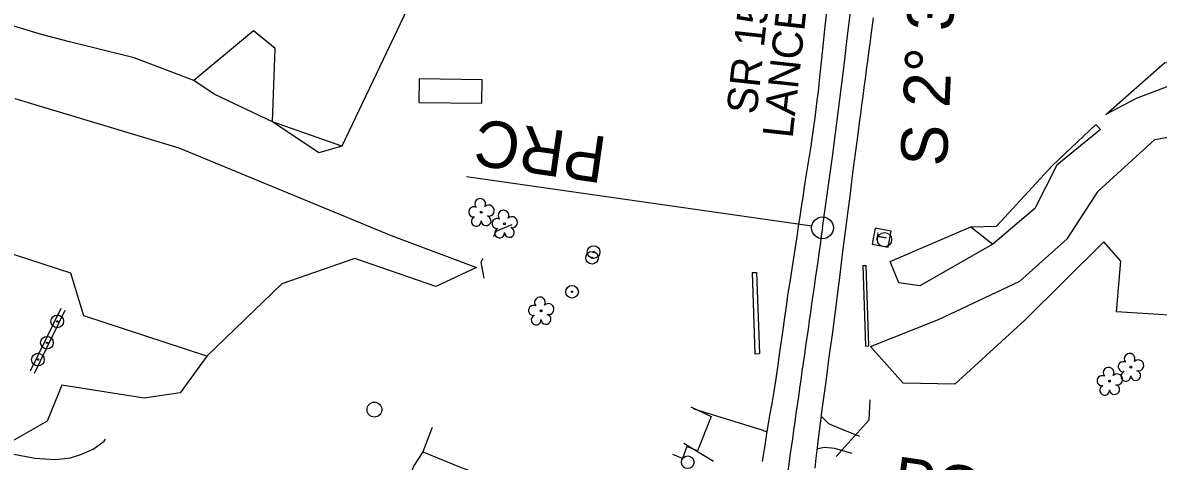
# Model space of a CAD drawing. Extents: x 478596 to 483012, y 490885 to 495165.
# Drawn here: x 480534.5 to 480925.2, y 493300.7 to 493451.6 of the extents above; entities that cross this region are included whole.
import ezdxf

# ---------------------------------------------------------------- set-up
doc = ezdxf.new("R2010")
doc.units = 0
for name, color, linetype in [('Exist Guardrail', 7, 'Continuous'), ('Exist Horizontal Alignment', 7, 'Continuous'), ('Exist Horizontal Alignment Direction Label', 7, 'Continuous'), ('Exist Other Culture AG Tank', 7, 'Continuous'), ('Exist Other Culture Area Outline', 7, 'Continuous'), ('Exist Other Culture Fence Line', 7, 'Continuous'), ('Exist Other Culture Gate', 7, 'Continuous'), ('Exist Other Culture Sign', 7, 'Continuous'), ('Exist Other Culture Sign Post CELL', 7, 'Continuous'), ('Exist Other Culture Well CELL', 7, 'Continuous'), ('Exist Roads Change in Surface', 7, 'Continuous'), ('Exist Roads EOP', 7, 'Continuous'), ('Exist Roads EOP Other', 7, 'Continuous'), ('Exist Roads EOP Text', 7, 'Continuous'), ('Exist Roads Soil', 7, 'Continuous'), ('Exist Structure Major Bridge WW', 7, 'Continuous'), ('Exist Structure Minor Head and End Wall', 7, 'Continuous'), ('Exist Utilities Other Located Object CELL', 7, 'Continuous'), ('Exist Utilities Other Pole CELL', 7, 'Continuous'), ('Exist Utilities Telephone Pedestal CELL', 7, 'Continuous'), ('Exist Vegetation Hedge Row', 7, 'Continuous'), ('Exist Vegetation Tree CELL', 7, 'Continuous'), ('Exist Vegetation Woods Line', 7, 'Continuous')]:
    doc.layers.add(name, color=color, linetype=linetype)

msp = doc.modelspace()

# ---------------------------------------------------------------- linework, layer by layer
at = {"layer": 'Exist Guardrail'}
msp.add_lwpolyline([(480479.19, 493318.23), (480506.27, 493309.62), (480518.25, 493306.1), (480530.88, 493303.33), (480538.59, 493301.85), (480545.76, 493301.36), (480550.94, 493301.88), (480554.47, 493303.03), (480558.73, 493304.94), (480562.47, 493307.62), (480563, 493308.29)], dxfattribs=at)
at = {"layer": 'Exist Horizontal Alignment'}
msp.add_line((480805.95, 493381.57), (480687.14, 493398.6), dxfattribs=at)
msp.add_circle((480809.67, 493381.04), 3.75, dxfattribs=at)
for centre, radius, start, end in [((478138.27, 493763.94), 2698.7, 351.84313, 357.4169), ((630504.98, 471924.64), 151225.21, 171.8431343, 171.8786811)]:
    msp.add_arc(centre, radius, start, end, dxfattribs=at)
at = {"layer": 'Exist Other Culture AG Tank'}
msp.add_lwpolyline([(480670.74, 493424.2), (480692.49, 493423.89), (480692.6, 493431.99), (480670.85, 493432.3)], close=True, dxfattribs=at)
at = {"layer": 'Exist Other Culture Area Outline'}
msp.add_lwpolyline([(480764.34, 493319.41), (480771.39, 493316.17), (480766.7, 493304.33), (480762.97, 493305.87), (480761.44, 493301.74), (480758.15, 493303.08)], dxfattribs=at)
at = {"layer": 'Exist Other Culture Fence Line'}
msp.add_line((480825.73, 493315.01), (480826.11, 493321.82), dxfattribs=at)
at = {"layer": 'Exist Other Culture Gate'}
msp.add_line((480825.73, 493315.01), (480814.35, 493302.4), dxfattribs=at)
at = {"layer": 'Exist Other Culture Sign'}
for p, q in [((480537.2, 493331.8), (480547.68, 493353.42)), ((480549.01, 493352.64), (480538.39, 493330.9))]:
    msp.add_line(p, q, dxfattribs=at)
at = {"layer": 'Exist Other Culture Sign Post CELL'}
for centre, radius in [((480546.36, 493348.84), 2.18), ((480546.36, 493348.84), 0.24), ((480542.79, 493341.51), 2.18), ((480542.79, 493341.51), 0.24), ((480539.68, 493335.73), 2.18), ((480539.68, 493335.73), 0.24)]:
    msp.add_circle(centre, radius, dxfattribs=at)
at = {"layer": 'Exist Other Culture Well CELL'}
msp.add_circle((480655.5, 493318.51), 2.56, dxfattribs=at)
at = {"layer": 'Exist Roads Change in Surface'}
msp.add_lwpolyline([(480672.19, 493304.04), (480685.32, 493298.61), (480708.69, 493289.73), (480727.92, 493282.31), (480747.36, 493274.45)], dxfattribs=at)
at = {"layer": 'Exist Roads EOP'}
for points in [[(480811.15, 493456.15), (480810.52, 493450.38), (480809.9, 493444.69), (480809.32, 493439.18), (480808.8, 493433.96), (480808.57, 493431.69), (480808.15, 493427.94), (480807.77, 493424.79), (480807.03, 493418.84), (480806.61, 493415.79), (480806.14, 493412.58), (480805.64, 493409.17), (480805.1, 493405.69), (480804.54, 493402.25), (480803.97, 493398.78), (480803.41, 493395.19), (480802.87, 493391.63), (480802.36, 493388.28), (480801.86, 493384.97), (480801.34, 493381.57), (480800.79, 493377.99), (480799.9, 493372.12), (480799.22, 493367.76), (480798.49, 493363.09), (480797.79, 493358.55), (480797.12, 493354.14), (480796.45, 493349.44), (480795.75, 493344.39), (480795.02, 493339.17), (480794.27, 493333.9), (480793.57, 493329.08), (480792.91, 493324.75), (480792.23, 493320.66), (480791.47, 493316.51), (480791.13, 493314.43), (480790.29, 493309.44), (480789.7, 493305.5), (480788.95, 493300.7)], [(480827.07, 493453.25), (480826.31, 493447.36), (480825.92, 493444.38), (480825.53, 493441.37), (480825.13, 493438.36), (480824.74, 493435.35), (480824.33, 493432.32), (480823.93, 493429.29), (480823.53, 493426.26), (480823.13, 493423.23), (480822.72, 493420.21), (480822.32, 493417.19), (480821.91, 493414.19), (480821.11, 493408.24), (480820.35, 493402.49), (480819.67, 493397.03), (480819.03, 493391.85), (480818.37, 493386.89), (480817.75, 493382.27), (480817.22, 493378.09), (480816.69, 493373.84), (480816.09, 493369.03), (480815.46, 493363.94), (480814.82, 493358.85), (480814.21, 493354.01), (480813.68, 493349.68), (480813.2, 493345.91), (480812.74, 493342.77), (480811.99, 493337.47), (480811.39, 493332.89), (480810.76, 493328.15), (480810.1, 493323.35), (480809.45, 493318.54), (480808.81, 493313.77), (480808.26, 493309.39), (480807.81, 493305.44), (480807.39, 493301.77), (480807, 493298.35)]]:
    msp.add_lwpolyline(points, dxfattribs=at)
at = {"layer": 'Exist Roads EOP Other'}
msp.add_lwpolyline([(480675.35, 493312.36), (480672.19, 493304.04), (480669.18, 493299.4), (480665.43, 493290.31), (480662.59, 493288.55)], dxfattribs=at)
at = {"layer": 'Exist Roads Soil'}
msp.add_line((480762, 493306.98), (480772.17, 493300.81), dxfattribs=at)
for points in [[(480790.44, 493310.85), (480788.89, 493311.38), (480765.5, 493318.66)], [(480809.38, 493315.98), (480811.74, 493313.72), (480815.72, 493312.05), (480822.37, 493309.43)], [(480819.84, 493303.43), (480813.87, 493305.17), (480810.35, 493305.53), (480808.05, 493305.07)]]:
    msp.add_lwpolyline(points, dxfattribs=at)
at = {"layer": 'Exist Structure Major Bridge WW'}
for points in [[(480696.55, 493378.11), (480697.33, 493379.85), (480702.92, 493382.22)], [(480693.23, 493363.69), (480692.2, 493369.19), (480692.87, 493370.59)]]:
    msp.add_lwpolyline(points, dxfattribs=at)
at = {"layer": 'Exist Structure Minor Head and End Wall'}
for p, q in [((480785.44, 493365.65), (480786.94, 493365.7)), ((480785.44, 493365.65), (480786.43, 493337.73)), ((480786.94, 493365.7), (480787.93, 493337.78)), ((480823.65, 493368.08), (480824.65, 493368.11)), ((480824.61, 493340.38), (480823.65, 493368.08)), ((480825.6, 493340.41), (480824.65, 493368.11)), ((480786.43, 493337.73), (480787.93, 493337.78)), ((480824.61, 493340.38), (480825.6, 493340.41))]:
    msp.add_line(p, q, dxfattribs=at)
at = {"layer": 'Exist Utilities Other Located Object CELL'}
for centre, radius in [((480730.36, 493370.73), 2.18), ((480730.88, 493372.69), 2.18), ((480730.88, 493372.69), 0.24), ((480730.36, 493370.73), 0.24), ((480723.5, 493359.03), 2.18), ((480723.5, 493359.03), 0.24), ((480763.29, 493300.42), 2.18)]:
    msp.add_circle(centre, radius, dxfattribs=at)
at = {"layer": 'Exist Utilities Other Pole CELL'}
msp.add_circle((480831, 493376.98), 2.46, dxfattribs=at)
at = {"layer": 'Exist Utilities Telephone Pedestal CELL'}
msp.add_line((480829.97, 493377.61), (480829.97, 493377.61), dxfattribs=at)
msp.add_lwpolyline([(480832.23, 493374.4), (480833.29, 493379.89), (480827.8, 493380.95), (480826.74, 493375.46), (480832.23, 493374.4)], dxfattribs=at)
at = {"layer": 'Exist Vegetation Hedge Row'}
for points in [[(480644.31, 493409.14), (480636.34, 493406.88), (480620.45, 493417.45), (480600.3, 493427.01), (480593.39, 493431.73)], [(480860.65, 493381.34), (480869.56, 493381.65), (480888.77, 493402.49), (480903.66, 493416.55), (480905.32, 493414.83), (480890.34, 493402.59), (480882.75, 493387.73), (480868.24, 493375.37)], [(480597.81, 493336.9), (480588.62, 493324.24), (480576.28, 493322.48), (480547.92, 493326.91), (480542.86, 493314.56), (480529.28, 493306.77), (480482.8, 493320.41)]]:
    msp.add_lwpolyline(points, dxfattribs=at)
at = {"layer": 'Exist Vegetation Tree CELL'}
for p, q in [((480692.26, 493386.38), (480692.26, 493386.38)), ((480700.28, 493382.38), (480700.28, 493382.38)), ((480712.82, 493352.48), (480712.82, 493352.48)), ((480915.74, 493333.11), (480915.74, 493333.11)), ((480908.47, 493328.3), (480908.47, 493328.3))]:
    msp.add_line(p, q, dxfattribs=at)
for centre in [(480692.26, 493386.38), (480700.28, 493382.38), (480712.82, 493352.48), (480915.74, 493333.11), (480908.47, 493328.3)]:
    msp.add_circle(centre, 0.326, dxfattribs=at)
for centre, radius, start, end in [((480689.66, 493386.54), 1.73, 62.6636, 279.3457), ((480691.88, 493389.26), 1.86, 330.1651, 219.7134), ((480694.81, 493386.97), 1.9, 257.1011, 134.1999), ((480690.56, 493383.26), 1.69, 111.5671, 6.231), ((480693.93, 493383.49), 1.7, 181.2822, 74.56), ((480697.68, 493382.53), 1.73, 62.6636, 279.3457), ((480699.9, 493385.25), 1.86, 330.1651, 219.7134), ((480702.83, 493382.97), 1.9, 257.1011, 134.1999), ((480698.58, 493379.26), 1.69, 111.5671, 6.231), ((480701.95, 493379.48), 1.7, 181.2822, 74.56), ((480712.44, 493355.35), 1.86, 330.1651, 219.7134), ((480710.22, 493352.63), 1.73, 62.6636, 279.3457), ((480715.37, 493353.07), 1.9, 257.1011, 134.1999), ((480711.12, 493349.36), 1.69, 111.5671, 6.231), ((480714.49, 493349.58), 1.7, 181.2822, 74.56), ((480915.35, 493335.99), 1.86, 330.1651, 219.7134), ((480913.13, 493333.27), 1.73, 62.6636, 279.3457), ((480918.29, 493333.7), 1.9, 257.1011, 134.1999), ((480905.86, 493328.45), 1.73, 62.6636, 279.3457), ((480908.08, 493331.17), 1.86, 330.1651, 219.7134), ((480911.01, 493328.89), 1.9, 257.1011, 134.1999), ((480914.03, 493329.99), 1.69, 111.5671, 6.231), ((480917.41, 493330.21), 1.7, 181.2822, 74.56), ((480906.76, 493325.18), 1.69, 111.5671, 6.231), ((480910.14, 493325.4), 1.7, 181.2822, 74.56)]:
    msp.add_arc(centre, radius, start, end, dxfattribs=at)
at = {"layer": 'Exist Vegetation Woods Line'}
for points in [[(480540.92, 493447.58), (480508.77, 493457.15), (480492.94, 493489.07), (480468.63, 493497.9), (480466.93, 493532.21), (480443.4, 493535.98), (480403.26, 493536.26), (480395.84, 493558.28), (480395.61, 493579.26), (480377.51, 493588.16), (480364.74, 493533.56), (480390.2, 493528.75), (480387.9, 493517.6), (480375.77, 493510.66), (480360.76, 493518.67), (480327.98, 493531.78), (480292.49, 493541.26), (480263.38, 493552.08), (480230.03, 493566.38), (480216.33, 493577.07), (480172.54, 493588.25), (480134.14, 493597.38), (480085.92, 493603.82), (480048.01, 493615.8)], [(480723.48, 493588.47), (480726.76, 493578.77), (480713.73, 493529.15), (480691.84, 493507.12), (480672.5, 493494.03), (480666.66, 493477.54), (480666.71, 493456.31), (480644.31, 493409.14)], [(480593.39, 493431.73), (480572.82, 493439.54), (480550.6, 493445.01), (480540.92, 493447.58)], [(480644.31, 493409.14), (480620.45, 493417.45), (480621.38, 493442.7), (480613.83, 493448.77), (480593.39, 493431.73)], [(480907.18, 493420.06), (480927.4, 493437.96), (480950.62, 493435.4)], [(480952.91, 493429.92), (480928.43, 493429.7), (480917.59, 493425.5), (480907.18, 493420.06)], [(480531.73, 493425.48), (480588.15, 493408.52), (480661.3, 493378.45), (480690.58, 493367.38), (480676.64, 493360.9), (480648.74, 493370.46), (480623.68, 493361.76), (480597.81, 493336.9), (480555.54, 493350.81), (480550.98, 493365.48), (480522.06, 493374.82), (480497.76, 493368.38)], [(480826.21, 493340.23), (480849.54, 493349.52), (480877.59, 493362.64), (480894.01, 493377.35), (480904.54, 493393.67), (480924, 493411.46), (480950.12, 493416.08)], [(481021.85, 493409.36), (481004.11, 493397.69), (480932.64, 493350.72), (480910.86, 493352.18), (480912.3, 493369.62), (480906.49, 493376.18), (480879.32, 493349.28)], [(480832.9, 493369.48), (480860.65, 493381.34), (480868.24, 493375.37)], [(480868.24, 493375.37), (480843.2, 493361.06), (480835.97, 493362.08), (480832.9, 493369.48)], [(480879.32, 493349.28), (480855.25, 493327.23), (480837.44, 493327.66), (480826.21, 493340.23)]]:
    msp.add_lwpolyline(points, dxfattribs=at)

# ---------------------------------------------------------------- texts
at = {"layer": 'Exist Horizontal Alignment'}
for s, rotation, p in [('PRC', 171.8431, (480736.03, 493412.17)), ('PCC', 351.8787, (480833.09, 493286.65))]:
    msp.add_text(s, height=16, rotation=rotation, dxfattribs=at).set_placement(p)
at = {"layer": 'Exist Horizontal Alignment Direction Label'}
msp.add_text('S 2%%d 34\' 59" W', height=16, rotation=87.4169, dxfattribs=at).set_placement((480852.42, 493401.97))
at = {"layer": 'Exist Roads EOP Text'}
for s, p in [('LANCE RD', (480799.33, 493411.63)), ('SR 1583', (480786.96, 493419.86))]:
    msp.add_text(s, height=10.4, rotation=83.7768, dxfattribs=at).set_placement(p)
at = {"layer": 'Exist Utilities Telephone Pedestal CELL'}
msp.add_text('T', height=3.42, rotation=79.0946, dxfattribs=at).set_placement((480831.44, 493376.18))

doc.saveas('drawing.dxf')
